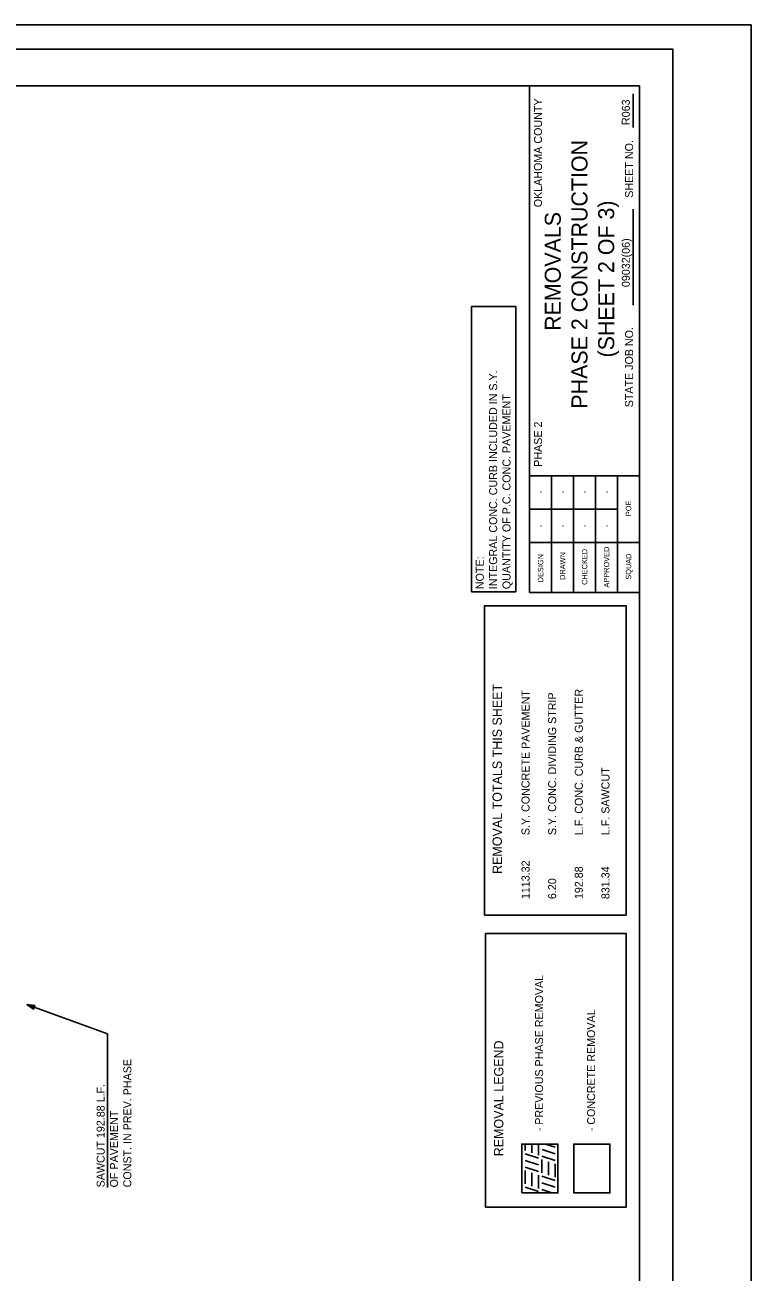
# Model space of a CAD drawing. Extents: x 2150259 to 2151459, y 143090 to 145092.
# Drawn here: x 2150914 to 2151459, y 144157 to 145092 of the extents above; entities that cross this region are included whole.
import ezdxf

# ---------------------------------------------------------------- set-up
doc = ezdxf.new("R2010")
doc.units = 0
for name, color, linetype in [('PR_Pattern_Area_Removal_Conc', 7, 'Continuous'), ('PR_Removal_Txt', 7, 'Continuous'), ('SHT_Plot_Shape_Full', 7, 'Continuous'), ('SHT_Plot_Shape_Half', 7, 'Continuous'), ('SHT_Sheet_Border', 7, 'Continuous'), ('SHT_Standard_Sheet_Lines', 7, 'Continuous'), ('SHT_Standard_Sheet_Txt', 7, 'Continuous'), ('SHT_Title_Sheet_Misc', 7, 'Continuous'), ('TYP_Typical_Section_Txt', 7, 'Continuous')]:
    doc.layers.add(name, color=color, linetype=linetype)

msp = doc.modelspace()

# ---------------------------------------------------------------- linework, layer by layer
at = {"layer": 'PR_Pattern_Area_Removal_Conc'}
for p, q in [((2151289.78, 144247.83), (2151289.78, 144252.78)), ((2151294.78, 144246.16), (2151294.78, 144252.78)), ((2151299.78, 144244.5), (2151299.78, 144252.78)), ((2151312.28, 144250.33), (2151304.92, 144252.78)), ((2151287.28, 144236.16), (2151287.28, 144246.16)), ((2151299.65, 144242.04), (2151289.78, 144245.33)), ((2151312.28, 144240.33), (2151302.28, 144243.66)), ((2151312.28, 144245.33), (2151302.4, 144248.62)), ((2151299.65, 144237.04), (2151289.78, 144240.33)), ((2151299.65, 144232.04), (2151289.78, 144235.33)), ((2151302.28, 144231.16), (2151302.28, 144241.16)), ((2151307.28, 144229.5), (2151307.28, 144239.5)), ((2151312.28, 144227.83), (2151312.28, 144237.83)), ((2151289.78, 144222.83), (2151289.78, 144232.83)), ((2151294.78, 144221.16), (2151294.78, 144231.16)), ((2151299.78, 144219.5), (2151299.78, 144229.5)), ((2151312.28, 144225.33), (2151302.28, 144228.66)), ((2151312.28, 144220.33), (2151302.28, 144223.66)), ((2151287.15, 144216.16), (2151287.15, 144221.21)), ((2151299.65, 144217.04), (2151289.78, 144220.33)), ((2151309.78, 144216.16), (2151302.28, 144218.66))]:
    msp.add_line(p, q, dxfattribs=at)
msp.add_lwpolyline([(2151353.23, 144216.16), (2151353.23, 144252.78), (2151326.16, 144252.78), (2151326.16, 144216.16), (2151353.23, 144216.16)], dxfattribs=at)
at = {"layer": 'PR_Removal_Txt'}
msp.add_line((2150976.09, 144220.24), (2150976.09, 144329.32), dxfattribs=at)
msp.add_lwpolyline([(2150915.66, 144357.32), (2150976.09, 144335.32), (2150976.09, 144329.32)], dxfattribs=at)
msp.add_lwpolyline([(2150915.66, 144357.32), (2150921.63, 144356.69), (2150920.64, 144353.96)], close=True, dxfattribs=at)
at = {"layer": 'SHT_Plot_Shape_Full'}
msp.add_lwpolyline([(2150259.22, 143292.05), (2150259.22, 145092.05), (2151459.22, 145092.05), (2151459.22, 143292.05)], close=True, dxfattribs=at)
at = {"layer": 'SHT_Plot_Shape_Half'}
msp.add_lwpolyline([(2150300.47, 143373.92), (2150300.47, 145073.92), (2151400.47, 145073.92), (2151400.47, 143373.92)], close=True, dxfattribs=at)
at = {"layer": 'SHT_Sheet_Border'}
for p, q in [((2151292.97, 144666.42), (2151292.97, 145046.42)), ((2151375.47, 144753.92), (2151292.93, 144753.92)), ((2151375.47, 144666.42), (2151292.97, 144666.42))]:
    msp.add_line(p, q, dxfattribs=at)
msp.add_lwpolyline([(2151375.47, 145046.42), (2151375.47, 143471.42), (2150325.47, 143471.42), (2150325.47, 145046.42)], close=True, dxfattribs=at)
at = {"layer": 'SHT_Standard_Sheet_Lines'}
for p, q in [((2151370.66, 145015.19), (2151370.66, 145040.32)), ((2151370.66, 144881.96), (2151370.66, 144953.97)), ((2151358.96, 144728.92), (2151292.93, 144728.92)), ((2151375.47, 144703.92), (2151292.93, 144703.92))]:
    msp.add_line(p, q, dxfattribs=at)
for points in [[(2151309.47, 144753.92), (2151309.47, 144666.42)], [(2151325.97, 144753.92), (2151325.97, 144666.42)], [(2151342.47, 144753.92), (2151342.47, 144666.42)], [(2151358.97, 144753.92), (2151358.97, 144666.42)]]:
    msp.add_lwpolyline(points, dxfattribs=at)
at = {"layer": 'SHT_Title_Sheet_Misc'}
for points in [[(2151249.49, 144666.91), (2151249.49, 144880.95), (2151282.6, 144880.95), (2151282.6, 144666.91)], [(2151259.11, 144424.51), (2151259.11, 144656.42), (2151365.47, 144656.42), (2151365.47, 144424.51)], [(2151259.97, 144205.39), (2151259.97, 144410.77), (2151365.47, 144410.77), (2151365.47, 144205.39)], [(2151287.15, 144216.16), (2151287.15, 144252.78), (2151314.22, 144252.78), (2151314.22, 144216.16)], [(2151326.16, 144216.16), (2151326.16, 144252.78), (2151353.23, 144252.78), (2151353.23, 144216.16)]]:
    msp.add_lwpolyline(points, close=True, dxfattribs=at)

# ---------------------------------------------------------------- texts
at = {"layer": 'PR_Removal_Txt'}
for s, height, p in [('REMOVAL TOTALS THIS SHEET', 7, (2151272.19, 144455.33)), ('S.Y. CONCRETE PAVEMENT', 6, (2151292.94, 144484.44)), ('S.Y. CONC. DIVIDING STRIP', 6, (2151312.94, 144484.44)), ('L.F. CONC. CURB & GUTTER', 6, (2151332.94, 144484.44)), ('L.F. SAWCUT', 6, (2151352.94, 144484.44)), ('1113.32', 6, (2151292.94, 144436.44)), ('192.88', 6, (2151332.94, 144436.44)), ('831.34', 6, (2151352.94, 144436.44)), ('6.20  ', 6, (2151312.94, 144436.44)), ('- PREVIOUS PHASE REMOVAL', 6, (2151303.12, 144262.35)), ('- CONCRETE REMOVAL', 6, (2151342.13, 144262.35)), ('REMOVAL LEGEND', 7, (2151273.34, 144243.56)), ('CONST. IN PREV. PHASE', 6, (2150994.09, 144220.24)), ('SAWCUT 192.88 L.F. ', 6, (2150974.09, 144220.24)), ('OF PAVEMENT', 6, (2150984.09, 144220.24))]:
    msp.add_text(s, height=height, rotation=90, dxfattribs=at).set_placement(p)
at = {"layer": 'SHT_Standard_Sheet_Txt'}
for s, height, p in [('OKLAHOMA COUNTY', 6, (2151302.3, 144955.33)), ('R063', 6, (2151368.2, 145016.97)), ('PHASE 2 CONSTRUCTION', 12, (2151336.44, 144804.28)), ('SHEET NO. ', 6, (2151370.66, 144962.45)), ('(SHEET 2 OF 3)', 12, (2151356.48, 144842.67)), ('REMOVALS', 12, (2151316.4, 144862.58)), ('09032(06)', 6, (2151368.2, 144895.43)), ('STATE JOB NO.', 6, (2151370.66, 144805.28)), ('PHASE 2', 6, (2151302.3, 144760.7)), ('-', 4, (2151303.2, 144740.87)), ('-', 4, (2151319.71, 144740.87)), ('-', 4, (2151336.22, 144740.87)), ('-', 4, (2151352.73, 144740.87)), ('POE', 4, (2151369.22, 144723.67)), ('-', 4, (2151303.2, 144715.45)), ('-', 4, (2151319.71, 144715.45)), ('-', 4, (2151336.22, 144715.45)), ('-', 4, (2151352.73, 144715.45)), ('DESIGN', 4, (2151303.22, 144674.03)), ('DRAWN', 4, (2151319.73, 144675.82)), ('CHECKED', 4, (2151336.24, 144672.07)), ('APPROVED', 4, (2151352.75, 144670.1)), ('SQUAD', 4, (2151369.25, 144675.99))]:
    msp.add_text(s, height=height, rotation=90, dxfattribs=at).set_placement(p)
at = {"layer": 'TYP_Typical_Section_Txt'}
for s, p in [('INTEGRAL CONC. CURB INCLUDED IN S.Y.', (2151268.64, 144668.9)), ('QUANTITY OF P.C. CONC. PAVEMENT', (2151278.66, 144668.9)), ('NOTE:', (2151258.62, 144668.9))]:
    msp.add_text(s, height=6, rotation=90, dxfattribs=at).set_placement(p)

doc.saveas('drawing.dxf')
